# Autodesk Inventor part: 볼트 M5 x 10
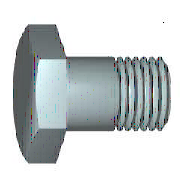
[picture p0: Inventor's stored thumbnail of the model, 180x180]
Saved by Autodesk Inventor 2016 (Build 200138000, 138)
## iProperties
IsCustomPart: 1
Created: 2012-02
Part Number: 볼트 M5 x 10
Material: 강철, 연강
Description: 6각 머리 볼트 및 6각 머리 나사
Document SubType Name: Modeling
Standard: KS B 1002
Designer: mduedu
Standards Organization: KS
Language: ko-KR
Size Designation: C  M 5 x 10
Categories: <MemberInstance><Categories><Category DisplayName="조임쇠" InternalName="e4da775c-781d-43d5-af7c-5136215cf5a6" Mnemonic="FSTN"><Category DisplayName="볼트" InternalN
Density: 1 g/cm^3
Appearance: 강철
Author: mduedu
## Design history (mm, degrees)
sketch "스케치1"
  geometry: L1 (0, 2.5)-(10, 2.5); L2 (10, 2.5)-(10, 0); L3 (10, 0)-(0, 0); L4 (-2, 0)-(12, 0) reference; L5 (0, -0.5)-(0, 3) reference; L6 (0, 2.5)-(0, 0)
  constraints: 8 end point, 3 point on line, 1 collinear
  dimensions: "d2" = 5 diameter of L1 L3 (= GD); "d59" = 10 distance between parallel lines of L2 L5 (= NLG)
revolve "본체" sketch "스케치1" stored, may be unused: angle "d12" = 90 deg
sketch "스케치2"
  geometry: L1 (0, 4.619)-(4, 2.309); L2 (4, 2.309)-(4, -2.309); L3 (4, -2.309)-(0, -4.619); L4 (0, -4.619)-(-4, -2.309); L5 (-4, -2.309)-(-4, 2.309); L6 (-4, 2.309)-(0, 4.619); L7 (-5.6, 0)-(5.6, 0) reference; L8 (0, 6.466)-(0, -6.466) reference; 2 further points
  constraints: 12 end point, 2 midpoint, 1 coincident, 1 vertical, 11 other
  dimensions: "d11" = 8 distance between parallel lines of L5 L2 (= SW)
extrude "머리" join sketch "스케치2" distance "d3" = 3.5 (= KOH); taper "d4" = 0 deg
revolve "모따기1" stored, may be unused: angle "d21" = 90 deg
workplane "Work Plane1"
body "Solid1"
feature "스레드" dims "d15" = 7.6 (= GEL), "d16" = 0
chamfer "모따기2" distance "d6" = 0.49076 (= -0.5 x SPD + 0.5 x GD); stored, may be unused: second distance "d7" = 0.49086 (computed from GUL), angle "d55" = 45 deg
sketch "스케치4"
  geometry: L1 (-3.038, 4.8)-(-3.5, 4); L2 (-1.1, 0)-(-0.234, 0); L3 (-4.153, 0)-(0.419, 0) reference; L4 (-3.5, 4.8)-(-3.038, 4.8); L5 (-3.5, 4)-(-3.5, 4.8); L6 (0, 5.76)-(0, -0.96) reference
  constraints: 8 end point, 1 parallel, 1 perpendicular, 1 point on line
  dimensions: "d65" = 8 diameter of L1.end L2 (= SW); "d67" = 30 deg angle of L1 L5 (= ANG1); "d68" = 9.6 diameter of L4 L2 (= 1.2 x SW); "d69" = 3.5 distance between parallel lines of L5 L6 (= KOH)
other parameters: "NLG" = 10 [user parameter; used in 1 equation term], "GD" = 5 (= NND) [user parameter; used in 2 equation terms], "BDM" = 5 (= NND) [user parameter], "KOH" = 3.5 [user parameter; used in 2 equation terms], "GEL" = 7.6 [user parameter; used in 1 equation term], "SW" = 8 [user parameter; used in 5 equation terms], "SW0" = 8 (= SW) [user parameter], "SPD" = 4.01848 (= NND - 1.2269 x PTC) [user parameter; used in 1 equation term], "SD2" = 5 (= NND) [user parameter], "SD" = 0 [user parameter], "ANG1" = 30 deg [user parameter; used in 1 equation term], "GAL" = 0.49076 (= 0.61345 x PTC) [user parameter], "GUL" = 0.49076 (= 0.61345 x PTC) [user parameter; used in 1 equation term], "d8" = 0, "RR" = 0.2 [user parameter], "d58" = 0, "RR1" = 0.1 [user parameter], "TPU" = 12.5 (computed from PTC) [user parameter], "GD1" = 4.01848 (= THREADDIA - 1.2269 x PTC) [user parameter], "THREADDIA" = 5 [user parameter; used in 1 equation term], "TOA" = 30 deg [user parameter], "PTC" = 0.8 [user parameter; used in 5 equation terms], "NND" = 5 [user parameter; used in 4 equation terms], "E0" = 9.24 (= 1.155 x SW) [user parameter]
